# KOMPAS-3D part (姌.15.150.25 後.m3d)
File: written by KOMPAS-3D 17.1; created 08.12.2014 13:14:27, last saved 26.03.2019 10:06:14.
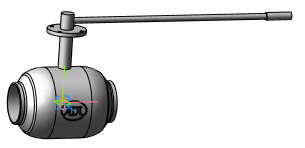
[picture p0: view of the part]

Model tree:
1. Операция без истории:4  (labels: Сталь 20  ГОСТ 1050-88)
